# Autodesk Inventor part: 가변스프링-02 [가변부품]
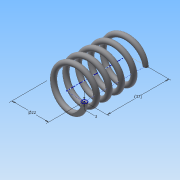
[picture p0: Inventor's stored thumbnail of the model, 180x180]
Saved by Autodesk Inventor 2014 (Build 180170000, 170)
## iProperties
Created: 2015-09
Part Number: 가변스프링-02 [가변부품]
Material: 강철, 탄소
Document SubType Name: Modeling
Designer: study
Density: 7.87 g/cm^3
Appearance: 반연마
Mass: 18.8111 g
Surface Area: 32.4633 cm^2
Volume: 2.39023 cm^3
Author: study
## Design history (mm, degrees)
sketch "스케치1"
  geometry: L1 (0, 0)-(11, 0); L2 (11, 0)-(11, 28.893); L3 (11, 28.893)-(0, 28.893); L4 (0, 28.893)-(0, 0); C1 r 1.5 at (11, 0)
  constraints: 8 end point, 2 parallel, 1 centre point, 1 coincident, 1 horizontal, 1 perpendicular
  dimensions: "d0" = 22 diameter of L2 L4; "d1" = 28.89259 distance of L1.end L2.end (derived); "d2" = 3 diameter of C1
feature "코일1" pitch "d3" = 10; turns "d5" = 5; dims "d4" = 28.89259 (= d1), "d6" = 0, angle "d7" = 90 deg, angle "d8" = 90 deg, "d9" = 0, "d10" = 0
node "작업 평면1"
sketch "스케치2"
  geometry: L1 (-12.5, 0)-(-9.5, 0) reference; 1 further point
  constraints: 1 horizontal alignment
extrude "돌출1" cut sketch "스케치2" stored distance "d12" = 10; taper "d13" = 0 deg
node "작업 평면2"
sketch "스케치3"
  geometry: L1 (-9.5, 0)-(-12.5, 0) reference; 1 further point
  constraints: 1 horizontal alignment
extrude "돌출2" cut sketch "스케치3" stored distance "d15" = 10; taper "d16" = 0 deg
node "솔리드1"
node "절단 모서리 투영1"
node "절단 모서리 투영2"
other parameters: "d11" = 0, "d14" = 28.89259 (= d1)
